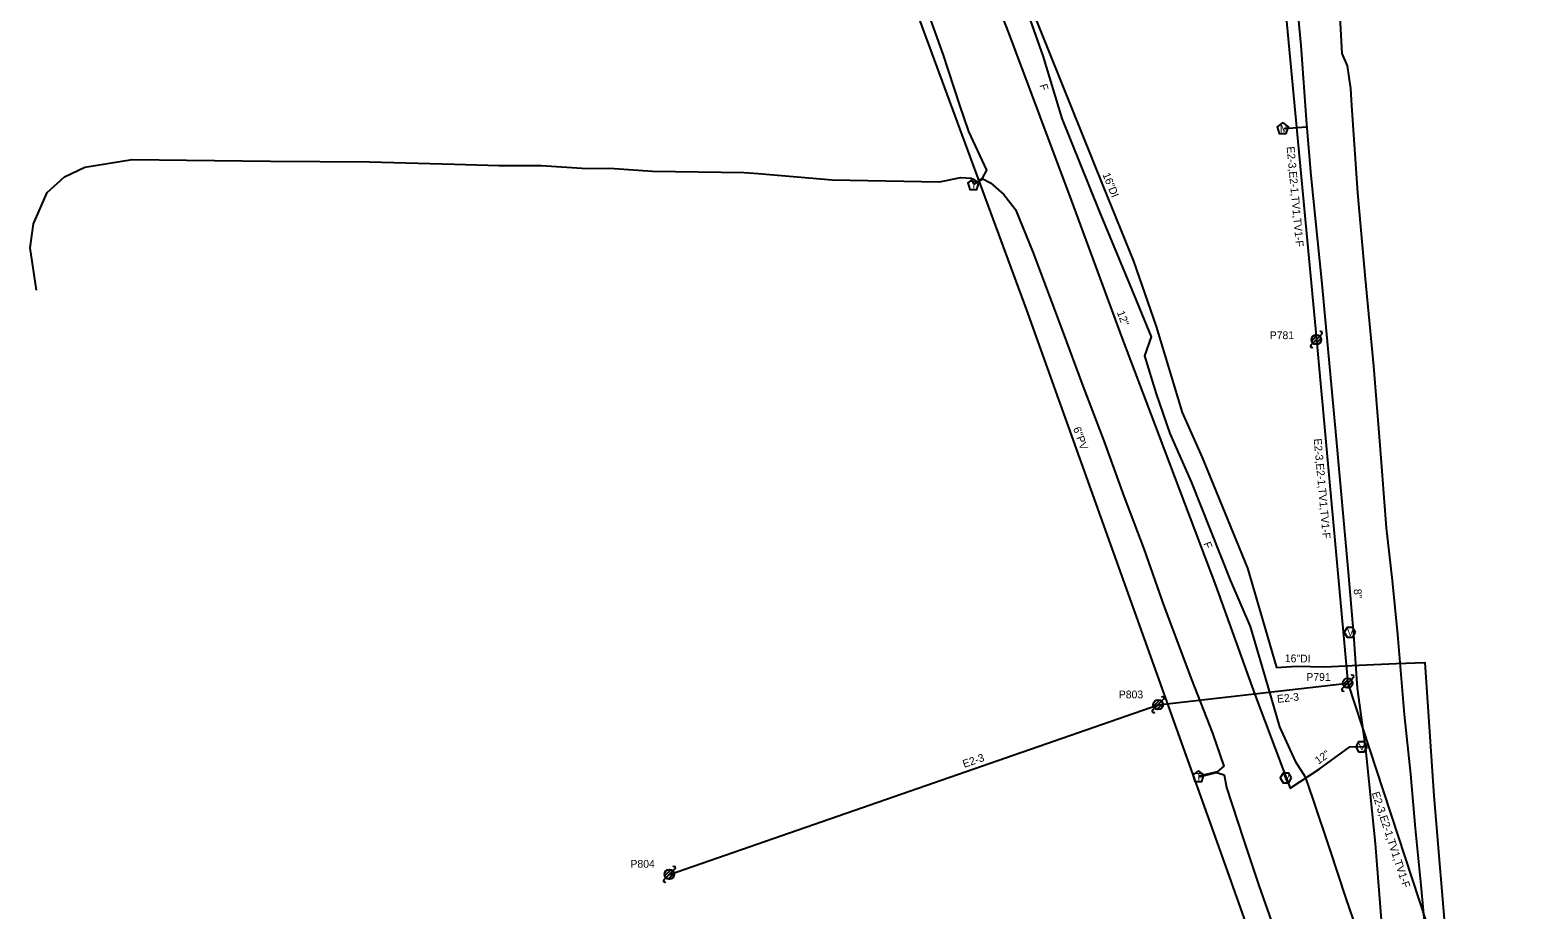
# Model space of a CAD drawing. Extents: x 1741604 to 1825760, y 1164229 to 1194908.
# Drawn here: x 1755713 to 1756488, y 1167064 to 1167516 of the extents above; entities that cross this region are included whole.
import ezdxf

# ---------------------------------------------------------------- set-up
doc = ezdxf.new("R2010")
doc.units = 0
for name, color, linetype in [('RD_EX_SU_H2O', 7, 'Continuous'), ('RD_EX_SU_Ovhd', 7, 'Continuous'), ('RD_EX_SU_Pole', 7, 'Continuous'), ('RD_EX_SU_Sewer', 7, 'Continuous'), ('RD_EX_SU_Telecom', 7, 'Continuous'), ('RD_EX_SU_TX_H2O', 7, 'Continuous'), ('RD_EX_SU_TX_Pole', 7, 'Continuous'), ('RD_EX_SU_TX_Sewer', 7, 'Continuous'), ('RD_EX_SU_TX_Telecom', 7, 'Continuous')]:
    doc.layers.add(name, color=color, linetype=linetype)

# ---------------------------------------------------------------- blocks, each defined once
blk = doc.blocks.new('SUE_WV')
at = {"layer": 'RD_EX_SU_H2O'}
blk.add_lwpolyline([(2.89, 0), (1.44, 2.5), (-1.44, 2.5), (-2.89, 0), (-1.44, -2.5), (1.44, -2.5)], close=True, dxfattribs=at)
blk.add_text('V', height=3.75, dxfattribs=at).set_placement((-1.43, -1.88))
blk = doc.blocks.new('SUE_TPP')
at = {"layer": 'RD_EX_SU_Telecom'}
blk.add_lwpolyline([(0, 3), (-2.85, 0.93), (-1.76, -2.43), (1.76, -2.43), (2.85, 0.93)], close=True, dxfattribs=at)
blk.add_text('T', height=3.75, dxfattribs=at).set_placement((-1.25, -1.88))
blk = doc.blocks.new('SUE_PP')
at = {"layer": 'RD_EX_SU_Pole'}
for p, q in [((-2.41, -0.65), (0.65, 2.41)), ((-1.77, -1.77), (1.77, 1.77)), ((-0.65, -2.41), (2.41, 0.65)), ((1.77, 1.77), (2.83, 2.83)), ((-2.83, -2.83), (-1.77, -1.77))]:
    blk.add_line(p, q, dxfattribs=at)
blk.add_circle((0, 0), 2.5, dxfattribs=at)
for centre, start, end in [((2.3, 3.36), 315, 135), ((-2.3, -3.36), 135, 315)]:
    blk.add_arc(centre, 0.75, start, end, dxfattribs=at)
blk = doc.blocks.new('SUE_WM')
at = {"layer": 'RD_EX_SU_H2O'}
blk.add_lwpolyline([(0, 3.05), (-2.9, 0.94), (-1.79, -2.47), (1.79, -2.47), (2.9, 0.94)], close=True, dxfattribs=at)
blk.add_text('M', height=3.75, dxfattribs=at).set_placement((-1.43, -1.88))

msp = doc.modelspace()

# ---------------------------------------------------------------- linework, layer by layer
at = {"layer": 'RD_EX_SU_H2O'}
msp.add_line((1756357.05, 1167465.19), (1756368.89, 1167466.14), dxfattribs=at)
for points in [[(1756050.84, 1167988.86), (1756081.08, 1167905.61), (1756101.58, 1167855.44), (1756116.98, 1167816.66), (1756140.78, 1167753.22), (1756156.44, 1167713.09), (1756172.97, 1167668.41), (1756185.91, 1167635.6), (1756220.9, 1167543.58), (1756264.25, 1167435.38), (1756279.82, 1167397.12), (1756291.55, 1167363.49), (1756304.82, 1167319.34), (1756315.11, 1167296.28), (1756338.43, 1167239.43), (1756353.36, 1167188.5), (1756363.56, 1167189.08), (1756377.88, 1167188.77), (1756395.74, 1167189.62), (1756414.79, 1167190.46), (1756429.52, 1167190.99), (1756434.13, 1167122.57), (1756440.84, 1167042.69)], [(1756071.31, 1167772.16), (1756085.11, 1167779.07), (1756108.91, 1167792.94), (1756111.78, 1167785), (1756127.48, 1167745.51), (1756138.1, 1167718.5), (1756155.05, 1167673.34), (1756169.44, 1167635.39), (1756195.1, 1167567.1), (1756215.65, 1167514.35), (1756247.83, 1167428.43), (1756274.14, 1167357.35), (1756290.72, 1167313.58), (1756321.91, 1167230.75), (1756342.14, 1167174.56), (1756357.52, 1167133.56), (1756360.24, 1167126.4), (1756375.13, 1167136.28), (1756391.03, 1167147.63), (1756398.81, 1167147.78)], [(1756363.91, 1167527.82), (1756365.79, 1167507.89), (1756368.78, 1167467.42), (1756370.98, 1167441.15), (1756376.52, 1167385.51), (1756383.76, 1167307.51), (1756390.19, 1167237.32), (1756392.83, 1167205.42), (1756394.81, 1167177.82), (1756398.97, 1167146.58), (1756403.93, 1167098.11), (1756407.85, 1167047.93), (1756412.78, 1166988.79), (1756417.67, 1166944.94), (1756423.69, 1166896.82), (1756432.52, 1166846.14), (1756436.46, 1166827.08), (1756441.46, 1166798.75), (1756455, 1166743.89), (1756461.58, 1166718.69), (1756465.96, 1166702.52), (1756470.95, 1166683.5), (1756477.35, 1166658.41), (1756487.5, 1166618.6)]]:
    msp.add_lwpolyline(points, dxfattribs=at)
at = {"layer": 'RD_EX_SU_Ovhd'}
for p, q in [((1756356.4, 1167543.03), (1756373.78, 1167356.82)), ((1756373.78, 1167356.82), (1756389.9, 1167180.4)), ((1756292.53, 1167169.29), (1756389.9, 1167180.4)), ((1756389.9, 1167180.4), (1756453.39, 1166987.51)), ((1756041.57, 1167082.19), (1756292.53, 1167169.29))]:
    msp.add_line(p, q, dxfattribs=at)
at = {"layer": 'RD_EX_SU_Sewer'}
msp.add_lwpolyline([(1756052.9, 1167838.38), (1756224.72, 1167372.47), (1756323.52, 1167096.55), (1756376.52, 1166947.01), (1756475.17, 1166587.83)], dxfattribs=at)
at = {"layer": 'RD_EX_SU_Telecom'}
for points in [[(1756379.84, 1167687.97), (1756371.61, 1167686.43), (1756371.04, 1167685.63), (1756373.7, 1167665.14), (1756377.25, 1167621.18), (1756381.27, 1167576.66), (1756385.09, 1167535.47), (1756386.8, 1167503.76), (1756389.57, 1167497.42), (1756391.33, 1167485.77), (1756391.87, 1167476.99), (1756394.9, 1167432.18), (1756398.78, 1167388.08), (1756403.08, 1167343.13), (1756406.4, 1167302.54), (1756409.67, 1167260.19), (1756412.65, 1167233.18), (1756415.46, 1167205.3), (1756418.94, 1167164.23), (1756422.06, 1167133.72), (1756424.59, 1167105.7), (1756427.38, 1167076.61), (1756430.2, 1167046.88)], [(1756127.86, 1167624.47), (1756134.12, 1167624.83), (1756137.29, 1167618.27), (1756151.91, 1167583.07), (1756167.31, 1167544.54), (1756181.93, 1167503.45), (1756190.52, 1167477.21), (1756195.07, 1167463.69), (1756198.66, 1167456.38), (1756204.33, 1167443.81), (1756202.19, 1167439.67), (1756198.01, 1167436.74)], [(1756219.98, 1167540.39), (1756233.26, 1167502.58), (1756243.02, 1167470.38), (1756262.18, 1167422.77), (1756277.81, 1167385.3), (1756288.97, 1167358.21), (1756285.51, 1167348.5), (1756291.55, 1167328.99), (1756298.55, 1167308.59), (1756309.54, 1167283.7), (1756329.67, 1167232.93), (1756339.86, 1167209.46), (1756347.48, 1167183.26), (1756354.82, 1167157.95), (1756362.81, 1167140.36), (1756367.98, 1167132.32), (1756372.03, 1167120.89), (1756380.69, 1167094.71), (1756388.9, 1167069.88), (1756396.35, 1167048.32)], [(1755716.66, 1167382.15), (1755713.32, 1167403.93), (1755715.11, 1167416.22), (1755722.13, 1167432.35), (1755730.94, 1167440.4), (1755741.48, 1167445.3), (1755765.63, 1167449.36), (1755793.63, 1167448.97), (1755836.82, 1167448.38), (1755887.65, 1167448.1), (1755931.3, 1167446.88), (1755953.98, 1167446.14), (1755975.83, 1167446.26), (1755999.21, 1167444.67), (1756010.84, 1167444.85), (1756032.85, 1167443.36), (1756079.89, 1167442.54), (1756087.21, 1167442.05), (1756125.23, 1167438.92), (1756152.76, 1167438.35), (1756180.34, 1167437.79), (1756191.2, 1167440.07), (1756196.45, 1167439.68), (1756197.64, 1167436.82)], [(1756197.87, 1167436.62), (1756202.53, 1167439.31), (1756206.5, 1167437.28), (1756213.34, 1167431.38), (1756219.24, 1167423.6), (1756228.33, 1167401.43), (1756243.69, 1167360.36), (1756253.54, 1167333.96), (1756264.59, 1167304.89), (1756274.92, 1167276.35), (1756285.26, 1167249.3), (1756295.42, 1167220.11), (1756309.65, 1167182.18), (1756320.43, 1167154.74), (1756326.22, 1167137.8), (1756322.81, 1167134.91), (1756313.46, 1167132.55)], [(1756313.58, 1167132.21), (1756322.47, 1167134.44), (1756326.44, 1167133.25), (1756327.61, 1167126.74), (1756336.38, 1167100.14), (1756344.24, 1167076.4), (1756353.92, 1167048.76), (1756360.54, 1167030.84), (1756366.88, 1167011.46), (1756375.52, 1166986.43), (1756383.22, 1166965.85)]]:
    msp.add_lwpolyline(points, dxfattribs=at)

# ---------------------------------------------------------------- block references
at = {"layer": 'RD_EX_SU_H2O'}
for name, p in [('SUE_WM', (1756356.55, 1167465.16)), ('SUE_WV', (1756390.98, 1167206.49)), ('SUE_WV', (1756396.89, 1167147.68)), ('SUE_WV', (1756358.15, 1167131.69))]:
    msp.add_blockref(name, p, dxfattribs=at)
at = {"layer": 'RD_EX_SU_Pole'}
for p in [(1756373.78, 1167356.82), (1756389.9, 1167180.4), (1756292.53, 1167169.29), (1756041.57, 1167082.19)]:
    msp.add_blockref('SUE_PP', p, dxfattribs=at)
at = {"layer": 'RD_EX_SU_Telecom'}
for p in [(1756197.62, 1167436.37), (1756313.17, 1167132.33)]:
    msp.add_blockref('SUE_TPP', p, dxfattribs=at)

# ---------------------------------------------------------------- texts
at = {"layer": 'RD_EX_SU_Ovhd'}
for s, rotation, p in [('E2-3,E2-1,TV1,TV1-F', 275.33068, (1756358.51, 1167455.8)), ('E2-3,E2-1,TV1,TV1-F', 275.22197, (1756372.41, 1167305.83)), ('E2-3', 6.51107, (1756353.81, 1167170.24)), ('E2-3', 19.13841, (1756192.96, 1167136.85)), ('E2-3,E2-1,TV1,TV1-F', 288.21877, (1756402.17, 1167123.92))]:
    msp.add_text(s, height=4, rotation=rotation, dxfattribs=at).set_placement(p)
at = {"layer": 'RD_EX_SU_TX_H2O'}
for s, rotation, p in [('16"DI', 292.14094, (1756263.88, 1167441.58)), ('12"', 290.31539, (1756271.29, 1167370.8)), ('8"', 274.73327, (1756392.92, 1167228.63)), ('16"DI', 358.78042, (1756357.54, 1167191.21)), ('12"', 35.52581, (1756374.79, 1167138.5))]:
    msp.add_text(s, height=4, rotation=rotation, dxfattribs=at).set_placement(p)
at = {"layer": 'RD_EX_SU_TX_Pole'}
for s, p in [('P781', (1756349.83, 1167357.03)), ('P791', (1756368.64, 1167181.56)), ('P803', (1756272.34, 1167172.59)), ('P804', (1756021.58, 1167085.6))]:
    msp.add_text(s, height=4, dxfattribs=at).set_placement(p)
at = {"layer": 'RD_EX_SU_TX_Sewer'}
msp.add_text('6"PV', height=4, rotation=289.70123, dxfattribs=at).set_placement((1756248.8, 1167311.16))
at = {"layer": 'RD_EX_SU_TX_Telecom'}
for rotation, p in [(286.86088, (1756231.58, 1167487.43)), (291.62563, (1756315.64, 1167252.05))]:
    msp.add_text('F', height=4, rotation=rotation, dxfattribs=at).set_placement(p)

doc.saveas('drawing.dxf')
